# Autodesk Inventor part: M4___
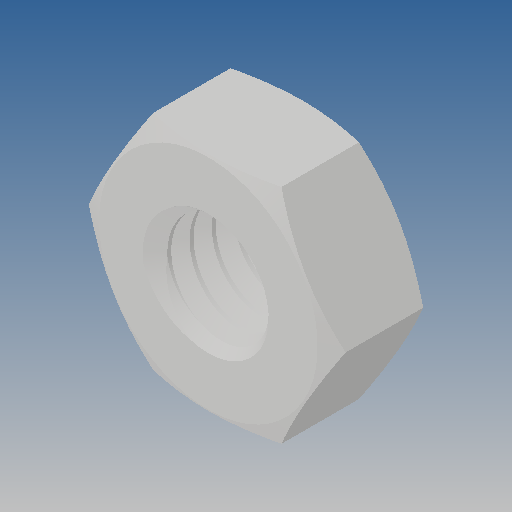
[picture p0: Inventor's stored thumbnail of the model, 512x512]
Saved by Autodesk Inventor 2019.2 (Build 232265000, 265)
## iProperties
Created: 2010-06
Part Number: M4___
Material: Ogólny
Document SubType Name: Modeling
Designer: CADENGINEERING4
Density: 1 g/cm^3
Appearance: Domyślna
Author: CADENGINEERING4
Revision Number: ANY
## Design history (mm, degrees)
feature "NONE"
node "Bryła1"
